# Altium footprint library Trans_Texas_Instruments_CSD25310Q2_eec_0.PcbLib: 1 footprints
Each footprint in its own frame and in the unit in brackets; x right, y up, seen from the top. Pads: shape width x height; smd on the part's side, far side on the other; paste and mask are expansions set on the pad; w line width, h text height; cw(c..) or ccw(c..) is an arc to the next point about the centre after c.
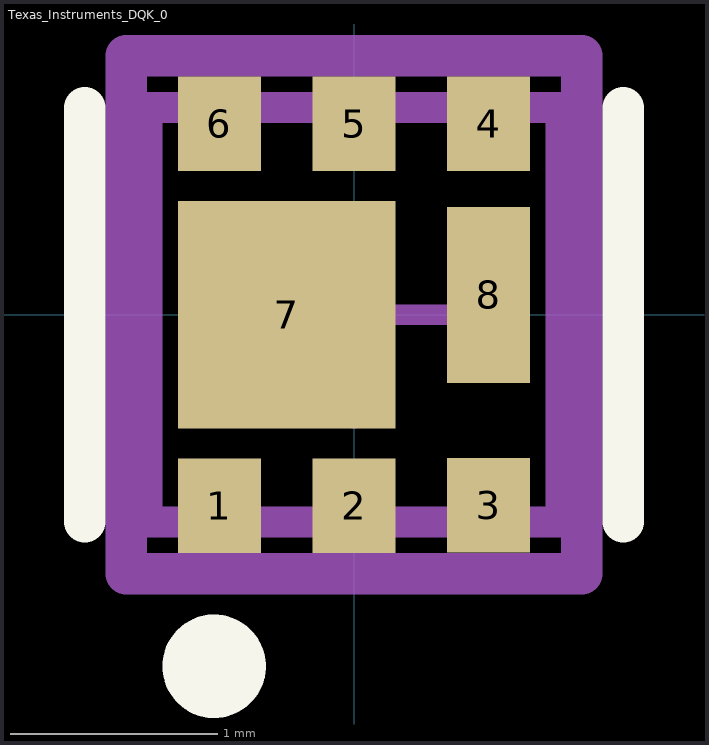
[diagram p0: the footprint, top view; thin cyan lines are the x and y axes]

## Texas_Instruments_DQK_0 [mm]
pads (8):
  rect 0.4x0.455 smd paste-1000 mask+0: 1(-0.65,-0.923) 2(0,-0.923) 3(0.65,-0.92) 4(0.65,0.923) 5(0,0.923) 6(-0.65,0.923)
  rect 1.05x1.1 smd paste-1000 mask+0: 7(-0.325,0)
  rect 0.4x0.85 smd paste-1000 mask+0: 8(0.65,0.096)
Top Overlay:
  circle w0.25: c-0.675,-1.697 r0.125
  lines w0.2: -1.3,-1 -1.3,1 ; 1.3,-1 1.3,1
Top Paste:
  rectangle: -0.8,-1.09 -0.5,-0.75
  rectangle: 0.5,-1.092 0.8,-0.753
  rectangle: 0.5,0.75 0.8,1.09
  rectangle: -0.8,0.75 -0.5,1.09
  rectangle: -0.15,0.75 0.15,1.09
  rectangle: -0.15,-1.09 0.15,-0.75
  rectangle: 0.5,-0.279 0.8,0.471
  rectangle: -0.8,-0.5 0.15,0.5
Mechanical 10:
  lines w0.2: -1.1,-1.25 1.1,-1.25 1.1,1.25 -1.1,1.25 -1.1,-1.25
  text ".Designator" at 0,0 h1
Mechanical 12:
  lines w0.15: -1,-1 1,-1 1,1 -1,1 -1,-1
Mechanical 15:
  lines w0.1: -0.5,0 0.5,0 ; -0.33,0 0.33,0 ; 0,-0.5 0,0.5 ; 0,-0.33 0,0.33
  lines w0.2: -1.1,-1.25 1.1,-1.25 1.1,1.25 -1.1,1.25 -1.1,-1.25
3D body "3dmodel.step": height 0.25, standoff 0, extent -1.1,-1.25 1.1,1.25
